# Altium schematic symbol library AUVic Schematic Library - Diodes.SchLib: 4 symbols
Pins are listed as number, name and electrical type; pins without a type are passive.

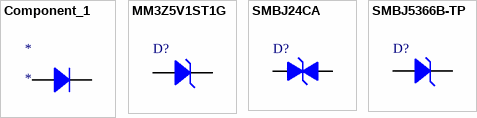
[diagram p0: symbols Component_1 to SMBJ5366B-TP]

## Component_1
designator *
pins: 1 Anode, 2 Cathode

## MM3Z5V1ST1G
designator D?  (value not drawn)
DIODE ZENER 5.1V 200MW SOD323; Manufacturer: ON Semiconductor; Manufacturer Part Number: MM3Z5V1ST1G; Tolerance: ±2%; Impedance (Max) (Zzt): 60 Ohm; Current - Reverse Leakage @ Vr: 2µA @ 2V; Voltage - Forward (Vf) (Max) @ If: 900mV @ 10mA
pins: 1 Anode, 2 Cathode

## SMBJ24CA
designator D?  (value not drawn)
TVS DIODE 24VWM 38.9VC SMB; Manufacturer: Fairchild Semiconductor; Manufacturer Part Number: SMBJ24CA; Type: Zener; Bidirectional Channels: 1; Voltage - Reverse Standoff (Typ): 24V; Voltage - Breakdown (Min): 26.7V; Voltage - Clamping (Max) @ Ipp: 38.9V; Current - Peak Pulse (10/1000µs): 15.4A; Power - Peak Pulse: 600W; Power Line Protection: No
footprint DO-214AC
pins: 1 Anode, 2 Cathode

## SMBJ5366B-TP
designator D?  (value not drawn)
DIODE ZENER 39V 5W DO214AA; Manufacturer: Micro Commercial Co; Manufacturer Part Number: SMBJ5366B-TP; Tolerance: ±5%; Impedance (Max) (Zzt): 14 Ohm; Current - Reverse Leakage @ Vr: 500nA @ 29.7V; Voltage - Forward (Vf) (Max) @ If: 1.2V @ 1A
footprint DO-214AC
pins: 1 Anode, 2 Cathode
